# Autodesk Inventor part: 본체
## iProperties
Company: 한국ATC센터
Created: 2014-10
Part Number: 본체
Document SubType Name: Modeling
Designer: 한국ATC센터
Density: 1 g/cm^3
Material: 기본값
Mass: 1088.52 g
Surface Area: 2150.09 cm^2
Volume: 1088.52 cm^3
Author: KYOUNG IL JANG
